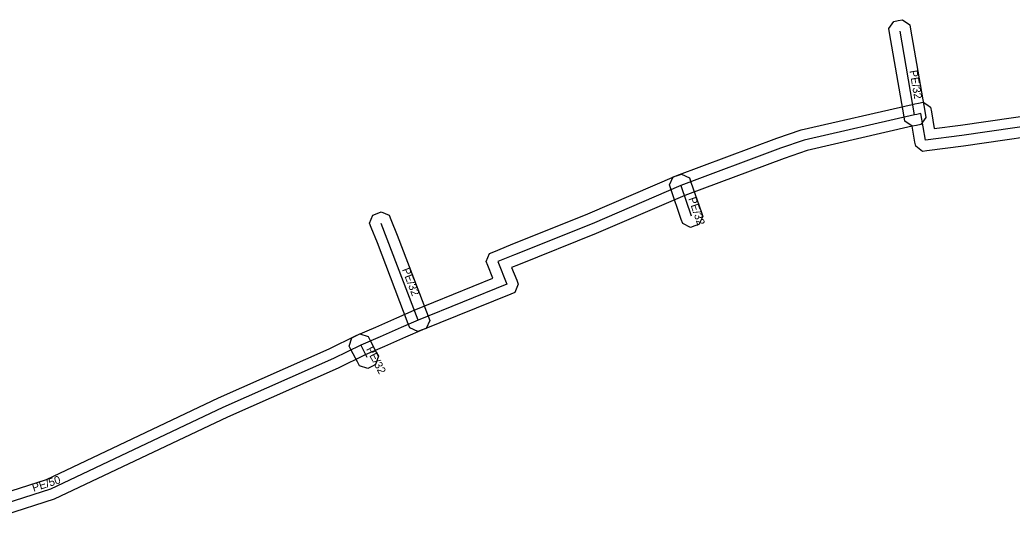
# Model space of a CAD drawing. Extents: x -682697 to -681888, y -1059966 to -1059631.
# Drawn here: x -682383.3 to -682290.2, y -1059839.2 to -1059791.2 of the extents above; entities that cross this region are included whole.
import ezdxf

# ---------------------------------------------------------------- set-up
doc = ezdxf.new("R2010")
doc.units = 0
for name, color, linetype in [('1', 7, 'Continuous'), ('24', 7, 'Continuous'), ('30', 7, 'Continuous')]:
    doc.layers.add(name, color=color, linetype=linetype)

msp = doc.modelspace()

# ---------------------------------------------------------------- linework, layer by layer
at = {"layer": '1'}
for points in [[(-682300.305, -1059800.708), (-682300.375, -1059800.3), (-682301.735, -1059792.44), (-682301.806, -1059792.032), (-682301.328, -1059791.355), (-682300.92, -1059791.285), (-682300.512, -1059791.214), (-682299.835, -1059791.692), (-682299.765, -1059792.1), (-682298.405, -1059799.96), (-682298.334, -1059800.368), (-682298.812, -1059801.045), (-682299.22, -1059801.115), (-682299.628, -1059801.186)], [(-682320.489, -1059806.043), (-682320.354, -1059806.435), (-682319.374, -1059809.285), (-682319.239, -1059809.676), (-682319.603, -1059810.421), (-682319.995, -1059810.556), (-682320.386, -1059810.691), (-682321.131, -1059810.327), (-682321.266, -1059809.935), (-682322.246, -1059807.085), (-682322.381, -1059806.694), (-682322.017, -1059805.949), (-682321.625, -1059805.814), (-682321.234, -1059805.679)], [(-682346.707, -1059820.124), (-682346.854, -1059819.737), (-682349.751, -1059812.145), (-682350.338, -1059810.682), (-682350.493, -1059810.298), (-682350.167, -1059809.536), (-682349.782, -1059809.382), (-682349.398, -1059809.227), (-682348.636, -1059809.553), (-682348.482, -1059809.938), (-682347.889, -1059811.415), (-682344.986, -1059819.023), (-682344.838, -1059819.41), (-682345.176, -1059820.167), (-682345.563, -1059820.314), (-682345.95, -1059820.462)], [(-682350.613, -1059820.922), (-682350.422, -1059821.29), (-682349.852, -1059822.39), (-682349.661, -1059822.758), (-682349.912, -1059823.547), (-682350.28, -1059823.738), (-682350.648, -1059823.929), (-682351.437, -1059823.678), (-682351.628, -1059823.31), (-682352.198, -1059822.21), (-682352.389, -1059821.842), (-682352.138, -1059821.053), (-682351.77, -1059820.862), (-682351.402, -1059820.671)]]:
    msp.add_lwpolyline(points, close=True, dxfattribs=at)
for points in [[(-682389.968, -1059837.272), (-682380.778, -1059834.328), (-682364.647, -1059826.681), (-682354.272, -1059822.083), (-682351.73, -1059820.842), (-682349.884, -1059820.035), (-682347.933, -1059819.165), (-682346.308, -1059818.458), (-682338.92, -1059815.459), (-682339.398, -1059814.274), (-682339.552, -1059813.891), (-682339.23, -1059813.13), (-682338.847, -1059812.974), (-682337.275, -1059812.333), (-682330.014, -1059809.417), (-682321.672, -1059805.832), (-682312.288, -1059802.329), (-682310.026, -1059801.547), (-682299.609, -1059799.154), (-682299.382, -1059799.104), (-682299.016, -1059799.024), (-682298.597, -1059798.931), (-682298.242, -1059799.17), (-682297.887, -1059799.409), (-682297.814, -1059799.831), (-682297.546, -1059801.399), (-682295.084, -1059801.089), (-682285.158, -1059799.648)], [(-682284.902, -1059801.632), (-682294.816, -1059803.071), (-682298.245, -1059803.502), (-682298.643, -1059803.552), (-682299.288, -1059803.074), (-682299.356, -1059802.679), (-682299.608, -1059801.206), (-682309.474, -1059803.473), (-682311.612, -1059804.211), (-682320.928, -1059807.688), (-682329.246, -1059811.263), (-682336.525, -1059814.187), (-682337.17, -1059814.45), (-682336.692, -1059815.636), (-682336.538, -1059816.019), (-682336.861, -1059816.781), (-682337.244, -1059816.937), (-682345.532, -1059820.302), (-682347.127, -1059820.995), (-682349.076, -1059821.865), (-682350.89, -1059822.658), (-682353.428, -1059823.897), (-682363.813, -1059828.499), (-682380.042, -1059836.192), (-682389.392, -1059839.188)]]:
    msp.add_lwpolyline(points, dxfattribs=at)
at = {"layer": '24'}
for points in [[(-682299.39, -1059800.13), (-682300.75, -1059792.27)], [(-682285.03, -1059800.64), (-682294.95, -1059802.08), (-682298.37, -1059802.51), (-682298.8, -1059800), (-682299.167, -1059800.081), (-682299.39, -1059800.13), (-682309.75, -1059802.51), (-682311.95, -1059803.27), (-682321.3, -1059806.76), (-682329.63, -1059810.34), (-682336.9, -1059813.26), (-682338.47, -1059813.9), (-682337.62, -1059816.01), (-682345.92, -1059819.38), (-682347.53, -1059820.08), (-682349.48, -1059820.95), (-682351.31, -1059821.75), (-682353.85, -1059822.99), (-682364.23, -1059827.59), (-682380.41, -1059835.26), (-682389.68, -1059838.23)], [(-682321.3, -1059806.76), (-682320.32, -1059809.61)], [(-682345.92, -1059819.38), (-682348.82, -1059811.78), (-682349.41, -1059810.31)], [(-682351.31, -1059821.75), (-682350.74, -1059822.85)]]:
    msp.add_lwpolyline(points, dxfattribs=at)

# ---------------------------------------------------------------- texts
at = {"layer": '30'}
for s, rotation, p in [('PE/32', 279.81658, (-682299.87, -1059796)), ('PE/32', 288.97603, (-682320.61, -1059807.985)), ('PE/32', 290.8858, (-682347.452, -1059814.64)), ('PE/32', 297.39237, (-682350.825, -1059822.1)), ('PE/50', 17.76485, (-682381.98, -1059835.499))]:
    msp.add_text(s, height=0.75, rotation=rotation, dxfattribs=at).set_placement(p)

doc.saveas('drawing.dxf')
